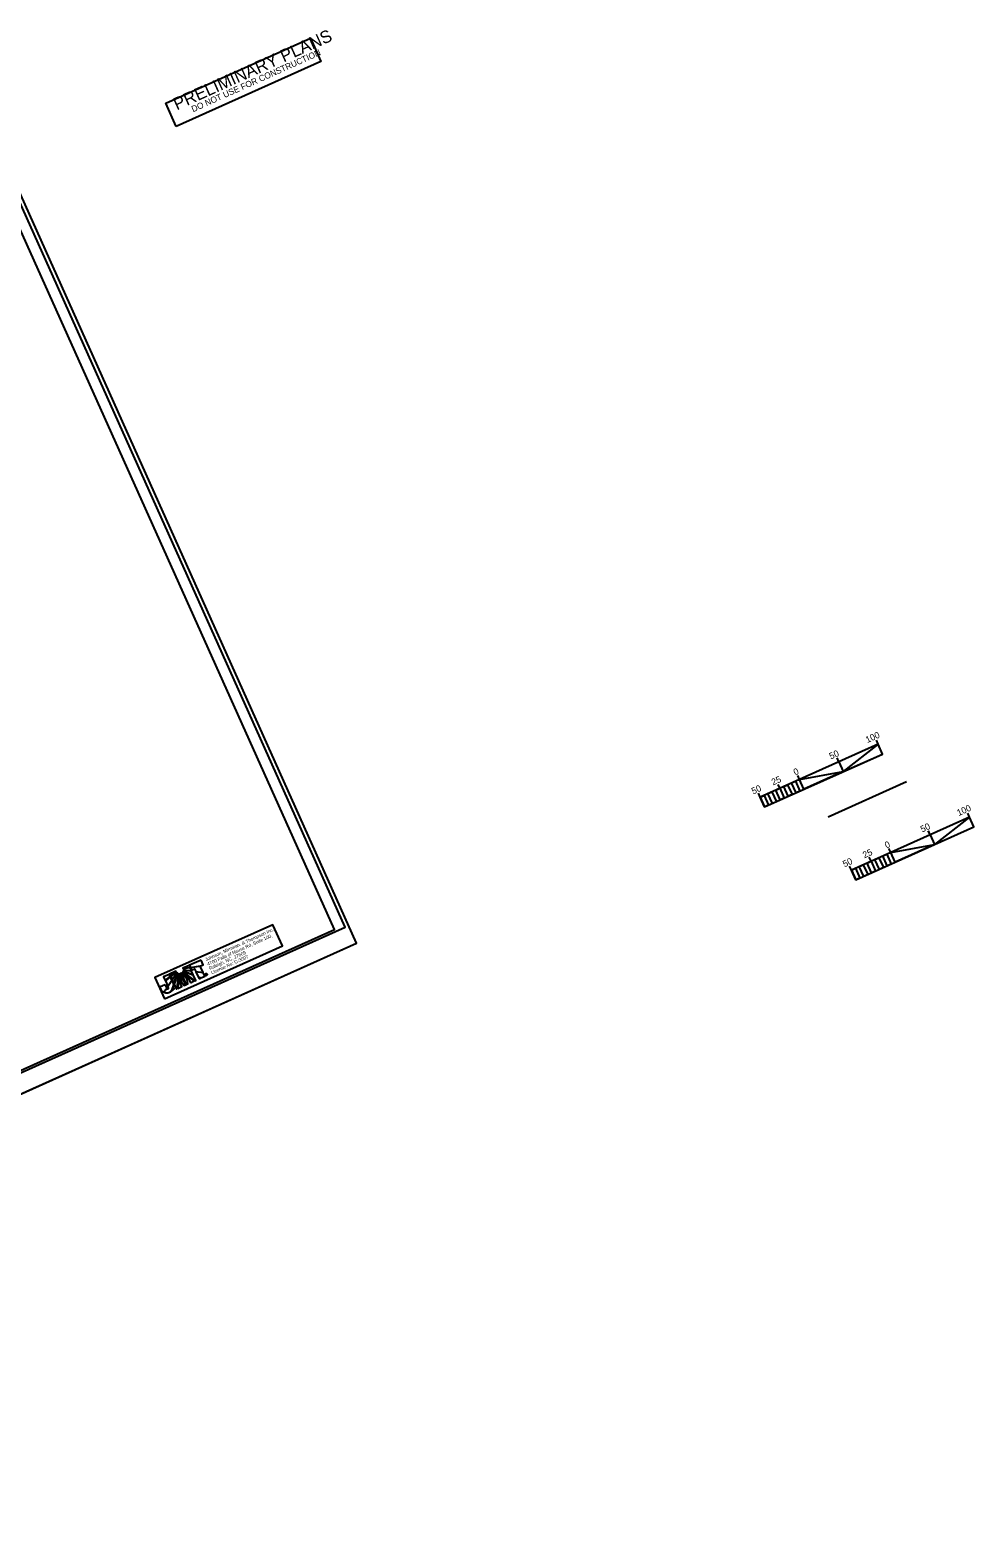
# Model space of a CAD drawing. Extents: x 553377 to 556641, y 502653 to 504402.
# Drawn here: x 555547 to 556641, y 502653 to 504402 of the extents above; entities that cross this region are included whole.
import ezdxf

# ---------------------------------------------------------------- set-up
doc = ezdxf.new("R2010")
doc.units = 0
for name, color, linetype in [('Prop Dimension', 7, 'Continuous'), ('Prop Dimension Text', 7, 'Continuous'), ('Sheet Border Standard 30in CELL', 7, 'Continuous'), ('Sheet Cutting Line CELL', 7, 'Continuous'), ('Sheet Data Field CELL', 7, 'Continuous'), ('Sheet Plot Border Inside CELL', 7, 'Continuous'), ('Sheet Plot Border Outside CELL', 7, 'Continuous'), ('Sheet Sticker Preliminary CELL', 7, 'Continuous'), ('Sheet Title CELL', 7, 'Continuous')]:
    doc.layers.add(name, color=color, linetype=linetype)

msp = doc.modelspace()

# ---------------------------------------------------------------- linework, layer by layer
at = {"layer": 'Prop Dimension'}
msp.add_line((556472.2, 503489.8), (556563.4, 503530.8), dxfattribs=at)
at = {"layer": 'Prop Dimension Text'}
for p, q in [((555731.2, 503317.3), (555724.1, 503314.2)), ((555732.3, 503315), (555731.2, 503317.3)), ((555745.2, 503323.6), (555731.7, 503317.6)), ((555731.7, 503317.6), (555732.8, 503315.1)), ((555732.8, 503315), (555744.8, 503316.8)), ((555744.2, 503316.3), (555733, 503314.6)), ((555747.4, 503309.2), (555744.2, 503316.3)), ((555744.8, 503316.8), (555747.6, 503318.1)), ((555747.6, 503318.1), (555745.2, 503323.6)), ((555708.1, 503306.9), (555701.7, 503304)), ((555701.7, 503304), (555703.6, 503299.8)), ((555703.6, 503299.8), (555709.2, 503304.4)), ((555709.4, 503304), (555703.8, 503299.3)), ((555703.8, 503299.3), (555706.5, 503293.3)), ((555706.5, 503293.3), (555711.1, 503300.3)), ((555709.2, 503304.4), (555708.1, 503306.9)), ((555715.9, 503310.5), (555708.7, 503307.2)), ((555708.7, 503307.2), (555709.8, 503304.9)), ((555711.1, 503300.3), (555709.4, 503304)), ((555709.8, 503304.9), (555714.5, 503308.8)), ((555714.7, 503308.3), (555710, 503304.4)), ((555710, 503304.4), (555711.6, 503301)), ((555711.6, 503301), (555715, 503306.2)), ((555715.8, 503306.4), (555711.8, 503300.4)), ((555711.8, 503300.4), (555713.6, 503296.4)), ((555713.6, 503296.4), (555717.2, 503306.5)), ((555717.6, 503306.3), (555713.9, 503295.8)), ((555714.5, 503308.8), (555715.9, 503310.5)), ((555716.7, 503309.5), (555714.7, 503308.3)), ((555715, 503306.2), (555716.7, 503309.5)), ((555717.7, 503308.8), (555715.8, 503306.4)), ((555717.2, 503306.5), (555717.7, 503308.8)), ((555718.7, 503308.3), (555717.6, 503306.3)), ((555717.6, 503290.4), (555718.6, 503302.2)), ((555718.6, 503302.2), (555717.8, 503303.9)), ((555717.8, 503303.9), (555718.6, 503302.9)), ((555719, 503301.3), (555718.1, 503290.6)), ((555718.6, 503302.9), (555718.9, 503305.9)), ((555718.9, 503305.9), (555718.7, 503308.3)), ((555722.9, 503292.8), (555719, 503301.3)), ((555719.4, 503306), (555719.1, 503302.4)), ((555719.1, 503302.4), (555721.8, 503299)), ((555719.9, 503308.2), (555719.4, 503306)), ((555720.6, 503306.1), (555719.9, 503308.2)), ((555721.8, 503299), (555720.6, 503306.1)), ((555723.6, 503303.5), (555721.1, 503308.4)), ((555721.1, 503308.4), (555721.1, 503305.9)), ((555721.1, 503305.9), (555722.5, 503298.2)), ((555722.2, 503308.9), (555724.1, 503303.7)), ((555723.9, 503307.2), (555722.2, 503308.9)), ((555723.1, 503309.6), (555724.2, 503307.6)), ((555725, 503308.5), (555723.1, 503309.6)), ((555727.5, 503294.9), (555723.6, 503303.5)), ((555723.7, 503310.6), (555725.4, 503308.9)), ((555726, 503310), (555723.7, 503310.6)), ((555728.9, 503301), (555723.9, 503307.2)), ((555724.1, 503314.2), (555726.3, 503314.1)), ((555724.1, 503311.7), (555726.1, 503310.5)), ((555727.1, 503311.6), (555724.1, 503311.7)), ((555724.1, 503303.7), (555727.9, 503295.1)), ((555726.3, 503313.6), (555724.2, 503312.9)), ((555724.2, 503312.9), (555727.9, 503311.9)), ((555724.2, 503307.6), (555728.8, 503301.9)), ((555728, 503306.3), (555725, 503308.5)), ((555725.4, 503308.9), (555727.9, 503307)), ((555736.4, 503305.8), (555726, 503310)), ((555726.1, 503310.5), (555736.1, 503306.4)), ((555726.3, 503314.1), (555732.3, 503315)), ((555732.5, 503314.5), (555726.3, 503313.6)), ((555734.2, 503310.5), (555727.1, 503311.6)), ((555727.9, 503307), (555727.7, 503308.4)), ((555727.7, 503308.4), (555728.5, 503306.5)), ((555727.9, 503311.9), (555734, 503311.1)), ((555728.8, 503301.9), (555728, 503306.3)), ((555728.5, 503306.5), (555737.8, 503299.5)), ((555737.3, 503299.3), (555728.9, 503305.6)), ((555728.9, 503305.6), (555732.7, 503297.3)), ((555729.7, 503295.9), (555728.9, 503301)), ((555734, 503311.1), (555732.5, 503314.5)), ((555732.7, 503297.3), (555737.3, 503299.3)), ((555732.8, 503315.1), (555732.8, 503315)), ((555733, 503314.6), (555733, 503314.6)), ((555733, 503314.6), (555734.2, 503312)), ((555734.2, 503312), (555737.5, 503313.5)), ((555736.1, 503306.4), (555734.2, 503310.5)), ((555738.9, 503300), (555736.4, 503305.8)), ((555737.5, 503313.5), (555738.9, 503310.4)), ((555737.8, 503299.5), (555738.9, 503300)), ((555738.9, 503310.4), (555747.4, 503309.2)), ((555739.1, 503309.9), (555741.7, 503304.2)), ((555747.6, 503308.7), (555739.1, 503309.9)), ((555741.7, 503304.2), (555745.1, 503302.8)), ((555744.4, 503302.5), (555742, 503303.6)), ((555742, 503303.6), (555742.8, 503301.8)), ((555742.8, 503301.8), (555744.4, 503302.5)), ((555745.1, 503302.8), (555749.4, 503304.7)), ((555749.4, 503304.7), (555747.6, 503308.7)), ((555750.4, 503307.1), (555750.8, 503307.3)), ((555750.8, 503306.1), (555750.4, 503307.1)), ((555750.5, 503307.8), (555750.6, 503307.6)), ((555750.6, 503307.6), (555750.5, 503307.8)), ((555750.9, 503307.1), (555750.7, 503307)), ((555750.7, 503307), (555750.8, 503306.8)), ((555750.8, 503307.3), (555750.9, 503307.1)), ((555750.9, 503307.1), (555750.8, 503307.3)), ((555750.8, 503307.3), (555750.8, 503307.3)), ((555750.8, 503306.8), (555751, 503306.8)), ((555751, 503306.2), (555750.8, 503306.1)), ((555750.9, 503307.1), (555750.9, 503307.1)), ((555751, 503306.7), (555750.9, 503306.6)), ((555750.9, 503306.6), (555751, 503306.2)), ((555751, 503306.8), (555751, 503306.7)), ((555751, 503306.7), (555751, 503306.8)), ((555751, 503306.8), (555751, 503306.8)), ((555751.1, 503306.7), (555751, 503306.7)), ((555751.4, 503305.9), (555751.5, 503305.7)), ((555751.5, 503305.7), (555751.4, 503305.9)), ((555751.4, 503305.9), (555751.4, 503305.9)), ((555751.5, 503305.7), (555751.5, 503305.7)), ((555713.9, 503295.8), (555716.5, 503289.9)), ((555716.5, 503289.9), (555717.6, 503290.4)), ((555718.1, 503290.6), (555722.9, 503292.8)), ((555722.5, 503298.2), (555725.7, 503294.1)), ((555725.7, 503294.1), (555727.5, 503294.9)), ((555727.9, 503295.1), (555729.7, 503295.9))]:
    msp.add_line(p, q, dxfattribs=at)
msp.add_lwpolyline([(555702.8, 503278.5), (555839.6, 503339.9), (555828.5, 503364.6), (555691.7, 503303.2)], close=True, dxfattribs=at)
for points in [[(555726.3, 503314.1), (555732.3, 503315), (555731.2, 503317.3), (555724.1, 503314.2), (555726.3, 503314.1)], [(555745.2, 503323.6), (555731.7, 503317.6), (555732.8, 503315.1), (555732.8, 503315), (555744.8, 503316.8), (555747.6, 503318.1), (555745.2, 503323.6)], [(555733, 503314.6), (555733, 503314.6), (555734.2, 503312), (555737.5, 503313.5), (555738.9, 503310.4), (555747.4, 503309.2), (555744.2, 503316.3), (555733, 503314.6)], [(555703.6, 503299.8), (555709.2, 503304.4), (555708.1, 503306.9), (555701.7, 503304), (555703.6, 503299.8)], [(555706.5, 503293.3), (555711.1, 503300.3), (555709.4, 503304), (555703.8, 503299.3), (555706.5, 503293.3)], [(555714.5, 503308.8), (555715.9, 503310.5), (555708.7, 503307.2), (555709.8, 503304.9), (555714.5, 503308.8)], [(555710, 503304.4), (555711.6, 503301), (555715, 503306.2), (555716.7, 503309.5), (555714.7, 503308.3), (555710, 503304.4)], [(555711.8, 503300.4), (555713.6, 503296.4), (555717.2, 503306.5), (555717.7, 503308.8), (555715.8, 503306.4), (555711.8, 503300.4)], [(555718.7, 503308.3), (555717.6, 503306.3), (555713.9, 503295.8), (555716.5, 503289.9), (555717.6, 503290.4), (555718.6, 503302.2), (555717.8, 503303.9), (555718.6, 503302.9), (555718.9, 503305.9), (555718.7, 503308.3)], [(555718.1, 503290.6), (555722.9, 503292.8), (555719, 503301.3), (555718.1, 503290.6)], [(555719.9, 503308.2), (555719.4, 503306), (555719.1, 503302.4), (555721.8, 503299), (555720.6, 503306.1), (555719.9, 503308.2)], [(555721.1, 503305.9), (555722.5, 503298.2), (555725.7, 503294.1), (555727.5, 503294.9), (555723.6, 503303.5), (555721.1, 503308.4), (555721.1, 503305.9)], [(555722.2, 503308.9), (555724.1, 503303.7), (555727.9, 503295.1), (555729.7, 503295.9), (555728.9, 503301), (555723.9, 503307.2), (555722.2, 503308.9)], [(555723.1, 503309.6), (555724.2, 503307.6), (555728.8, 503301.9), (555728, 503306.3), (555725, 503308.5), (555723.1, 503309.6)], [(555723.7, 503310.6), (555725.4, 503308.9), (555727.9, 503307), (555727.7, 503308.4), (555728.5, 503306.5), (555737.8, 503299.5), (555738.9, 503300), (555736.4, 503305.8), (555726, 503310), (555723.7, 503310.6)], [(555724.1, 503311.7), (555726.1, 503310.5), (555736.1, 503306.4), (555734.2, 503310.5), (555727.1, 503311.6), (555724.1, 503311.7)], [(555724.2, 503312.9), (555727.9, 503311.9), (555734, 503311.1), (555732.5, 503314.5), (555726.3, 503313.6), (555724.2, 503312.9)], [(555732.7, 503297.3), (555737.3, 503299.3), (555728.9, 503305.6), (555732.7, 503297.3)], [(555739.1, 503309.9), (555741.7, 503304.2), (555745.1, 503302.8), (555749.4, 503304.7), (555747.6, 503308.7), (555739.1, 503309.9), (555739.1, 503309.9)], [(555742.8, 503301.8), (555742.8, 503301.8), (555744.4, 503302.5), (555742, 503303.6), (555742.8, 503301.8)], [(555751.5, 503306.7), (555751.6, 503306.7), (555751.6, 503306.6), (555751.6, 503306.6), (555751.7, 503306.5), (555751.5, 503306.4)]]:
    msp.add_lwpolyline(points, dxfattribs=at)
for points, degree in [([(555706.8, 503290.3), (555706.4, 503290.1), (555705.9, 503290.2), (555705.5, 503290.9), (555705.5, 503290.9), (555702.2, 503285.9), (555702.2, 503285.9), (555704.3, 503285.1), (555706.9, 503285.2), (555708.8, 503286.1), (555709.3, 503286.3), (555709.7, 503286.5), (555710.2, 503286.9), (555710.2, 503286.9), (555713.3, 503295.4), (555713.3, 503295.4), (555713.3, 503295.4), (555711.3, 503299.7), (555711.3, 503299.7), (555711.3, 503299.7), (555706.7, 503292.8), (555706.7, 503292.8), (555707.5, 503291.2), (555707.3, 503290.6), (555706.8, 503290.3)], 3), ([(555706.8, 503290.3), (555706.4, 503290.1), (555705.9, 503290.2), (555705.5, 503290.9), (555705.5, 503290.9), (555702.2, 503285.9), (555702.2, 503285.9), (555704.3, 503285.1), (555706.9, 503285.2), (555708.8, 503286.1), (555709.3, 503286.3), (555709.7, 503286.5), (555710.2, 503286.9), (555710.2, 503286.9), (555713.3, 503295.4), (555713.3, 503295.4), (555713.3, 503295.4), (555711.3, 503299.7), (555711.3, 503299.7), (555711.3, 503299.7), (555706.7, 503292.8), (555706.7, 503292.8), (555707.5, 503291.2), (555707.3, 503290.6), (555706.8, 503290.3)], 3), ([(555751.5, 503305.7), (555751.2, 503305.6), (555750.9, 503305.5), (555750.6, 503305.7), (555750.3, 503305.8), (555750, 503306), (555749.9, 503306.3), (555749.8, 503306.6), (555749.8, 503306.9), (555749.9, 503307.2), (555750, 503307.5), (555750.2, 503307.7), (555750.5, 503307.8)], 3), ([(555750.6, 503307.6), (555750.4, 503307.5), (555750.2, 503307.4), (555750.1, 503307.1), (555750, 503306.9), (555750, 503306.6), (555750.1, 503306.4), (555750.2, 503306.1), (555750.4, 503306), (555750.7, 503305.9), (555750.9, 503305.8), (555751.2, 503305.8), (555751.4, 503305.9)], 3), ([(555750.5, 503307.8), (555750.8, 503308), (555751.1, 503308), (555751.4, 503307.9), (555751.7, 503307.8), (555752, 503307.6), (555752.1, 503307.3)], 3), ([(555751.4, 503305.9), (555751.6, 503306), (555751.8, 503306.2), (555751.9, 503306.4), (555752, 503306.7), (555752, 503306.9), (555751.9, 503307.2), (555751.8, 503307.4), (555751.6, 503307.6), (555751.3, 503307.7), (555751.1, 503307.8), (555750.9, 503307.7), (555750.6, 503307.6)], 3), ([(555750.8, 503307.3), (555751.1, 503307.4), (555751.3, 503307.4), (555751.3, 503307.2), (555751.4, 503307.1), (555751.4, 503307), (555751.3, 503306.9)], 3), ([(555751, 503306.8), (555751.1, 503306.9), (555751.2, 503307), (555751.1, 503307.1), (555751.1, 503307.1), (555751, 503307.1), (555750.9, 503307.1)], 3), ([(555751.2, 503306.7), (555751.2, 503306.7), (555751.1, 503306.7), (555751.1, 503306.7)], 2), ([(555751.5, 503306.4), (555751.4, 503306.4), (555751.4, 503306.5), (555751.4, 503306.6), (555751.3, 503306.6), (555751.3, 503306.7), (555751.2, 503306.7)], 3), ([(555751.3, 503306.9), (555751.4, 503306.9), (555751.5, 503306.8), (555751.5, 503306.7)], 2), ([(555752.1, 503307.3), (555752.2, 503307), (555752.2, 503306.7), (555752.1, 503306.4), (555752, 503306.1), (555751.8, 503305.8), (555751.5, 503305.7)], 3), ([(555703.4, 503295.2), (555703.4, 503295.2), (555697.5, 503292.6), (555697.5, 503292.6), (555697.5, 503292.6), (555699.2, 503288.9), (555699.2, 503288.9), (555699.2, 503288.9), (555699.4, 503288.5), (555699.4, 503288.5), (555699.9, 503287.3), (555700.7, 503286.6), (555701.7, 503286.1), (555701.7, 503286.1), (555705.2, 503291.2), (555705.2, 503291.3), (555705.2, 503291.3), (555703.4, 503295.2), (555703.4, 503295.2)], 3), ([(555713.6, 503294.7), (555713.6, 503294.7), (555710.9, 503287.4), (555710.9, 503287.4), (555713.1, 503289.1), (555714.8, 503291.8), (555713.6, 503294.7)], 3)]:
    msp.add_open_spline(points, degree=degree, dxfattribs=at)
at = {"layer": 'Sheet Border Standard 30in CELL'}
msp.add_lwpolyline([(555469.6, 504316.8), (554101.2, 503702.4), (554531.3, 502744.5), (555899.7, 503359)], close=True, dxfattribs=at)
at = {"layer": 'Sheet Cutting Line CELL'}
msp.add_line((554389.2, 502653.3), (555925.5, 503343.1), dxfattribs=at)
at = {"layer": 'Sheet Data Field CELL'}
for p, q in [((556530.4, 503574.1), (556528.3, 503578.6)), ((556484.7, 503553.6), (556482.7, 503558.1)), ((556416.3, 503522.8), (556414.3, 503527.4)), ((556393.5, 503512.6), (556391.5, 503517.2)), ((556636.2, 503489.4), (556634.2, 503494)), ((556590.6, 503468.9), (556588.6, 503473.5)), ((556522.2, 503438.2), (556520.1, 503442.8)), ((556499.4, 503428), (556497.3, 503432.5))]:
    msp.add_line(p, q, dxfattribs=at)
at = {"layer": 'Sheet Plot Border Inside CELL'}
msp.add_lwpolyline([(555480, 504324.3), (553959.7, 503641.6), (554391.9, 502679.1), (555912.2, 503361.8)], close=True, dxfattribs=at)
at = {"layer": 'Sheet Plot Border Outside CELL'}
msp.add_lwpolyline([(555474.9, 504346.6), (553938.6, 503656.8), (554389.2, 502653.3), (555925.5, 503343.1)], close=True, dxfattribs=at)
at = {"layer": 'Sheet Sticker Preliminary CELL'}
msp.add_lwpolyline([(555716.3, 504290.7), (555704.3, 504317.5), (555871.9, 504392.8), (555883.9, 504366)], close=True, dxfattribs=at)
at = {"layer": 'Sheet Title CELL'}
for p, q in [((556530.3, 503574.1), (556528.3, 503578.6)), ((556530.3, 503574.1), (556393.5, 503512.6)), ((556398.6, 503501.2), (556535.5, 503562.6)), ((556535.5, 503562.6), (556530.3, 503574.1)), ((556484.7, 503553.6), (556482.7, 503558.1)), ((556484.7, 503553.6), (556489.9, 503542.2)), ((556416.3, 503522.8), (556414.3, 503527.4)), ((556425.4, 503526.9), (556430.6, 503515.5)), ((556439.1, 503533.1), (556437.1, 503537.6)), ((556393.5, 503512.6), (556391.5, 503517.1)), ((556393.5, 503512.6), (556398.6, 503501.2)), ((556636.2, 503489.4), (556634.2, 503494)), ((556636.2, 503489.4), (556499.4, 503428)), ((556504.5, 503416.6), (556641.3, 503478)), ((556641.3, 503478), (556636.2, 503489.4)), ((556590.6, 503468.9), (556588.5, 503473.5)), ((556590.6, 503468.9), (556595.7, 503457.5)), ((556522.2, 503438.2), (556520.1, 503442.8)), ((556531.3, 503442.3), (556536.4, 503430.9)), ((556545, 503448.4), (556542.9, 503453)), ((556499.4, 503428), (556497.3, 503432.5)), ((556499.4, 503428), (556504.5, 503416.6))]:
    msp.add_line(p, q, dxfattribs=at)
for points in [[(556530.3, 503574.1), (556489.9, 503542.2), (556535.5, 503562.6)], [(556420.9, 503524.9), (556425.4, 503526.9), (556430.6, 503515.5), (556426, 503513.5)], [(556430, 503529), (556434.6, 503531), (556439.7, 503519.6), (556435.1, 503517.6)], [(556439.1, 503533.1), (556489.9, 503542.2), (556444.2, 503521.7)], [(556393.5, 503512.6), (556398.1, 503514.6), (556403.2, 503503.2), (556398.6, 503501.2)], [(556402.6, 503516.7), (556407.2, 503518.7), (556412.3, 503507.3), (556407.8, 503505.3)], [(556411.8, 503520.8), (556416.3, 503522.8), (556421.4, 503511.4), (556416.9, 503509.4)], [(556636.2, 503489.4), (556595.7, 503457.5), (556641.3, 503478)], [(556545, 503448.4), (556595.7, 503457.5), (556550.1, 503437)], [(556526.7, 503440.2), (556531.3, 503442.3), (556536.4, 503430.9), (556531.9, 503428.8)], [(556535.9, 503444.3), (556540.4, 503446.4), (556545.5, 503435), (556541, 503432.9)], [(556499.4, 503428), (556503.9, 503430), (556509.1, 503418.6), (556504.5, 503416.6)], [(556508.5, 503432.1), (556513.1, 503434.1), (556518.2, 503422.7), (556513.6, 503420.6)], [(556517.6, 503436.1), (556522.2, 503438.2), (556527.3, 503426.8), (556522.7, 503424.7)]]:
    msp.add_lwpolyline(points, close=True, dxfattribs=at)

# ---------------------------------------------------------------- texts
at = {"layer": 'Prop Dimension Text'}
for s, p in [('Johnson, Mirmiran, & Thompson Inc.', (555750.9, 503322.1)), ('4700 Falls of Neuse Rd, Suite 100, ', (555753.2, 503316.9)), ('Raleigh, NC, 27609', (555755.4, 503312)), ('License No: C-3097', (555757.7, 503307))]:
    msp.add_text(s, height=3.833, rotation=24.1816, dxfattribs=at).set_placement(p)
at = {"layer": 'Sheet Sticker Preliminary CELL'}
for s, height, p in [('PRELIMINARY PLANS', 14.4, (555717, 504309.1)), ('DO NOT USE FOR CONSTRUCTION', 7.2, (555735.9, 504307))]:
    msp.add_text(s, height=height, rotation=24.1816, dxfattribs=at).set_placement(p)
at = {"layer": 'Sheet Title CELL'}
for s, p in [('100', (556517.8, 503575.2)), ('50', (556475.6, 503556.2)), ('0', (556434.1, 503537.6)), ('50', (556385.5, 503515.7)), ('25', (556408.6, 503526.1)), ('100', (556623.7, 503490.5)), ('50', (556581.4, 503471.5)), ('0', (556540, 503452.9)), ('50', (556491.3, 503431.1)), ('25', (556514.4, 503441.5))]:
    msp.add_text(s, height=7.5, rotation=24.1864, dxfattribs=at).set_placement(p)

doc.saveas('drawing.dxf')
